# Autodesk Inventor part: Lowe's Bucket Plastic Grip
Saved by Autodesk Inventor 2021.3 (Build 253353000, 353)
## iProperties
Created: 2022-12
Part Number: Lowe's Bucket Plastic Grip
Material: Generic
Document SubType Name: Modeling
Designer: AdminForWorker
Density: 1 g/cm^3
Appearance: Default
Title: Lowe's Bucket Plastic Grip
Author: AdminForWorker
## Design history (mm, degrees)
feature "Body1"
body "Solid1"
